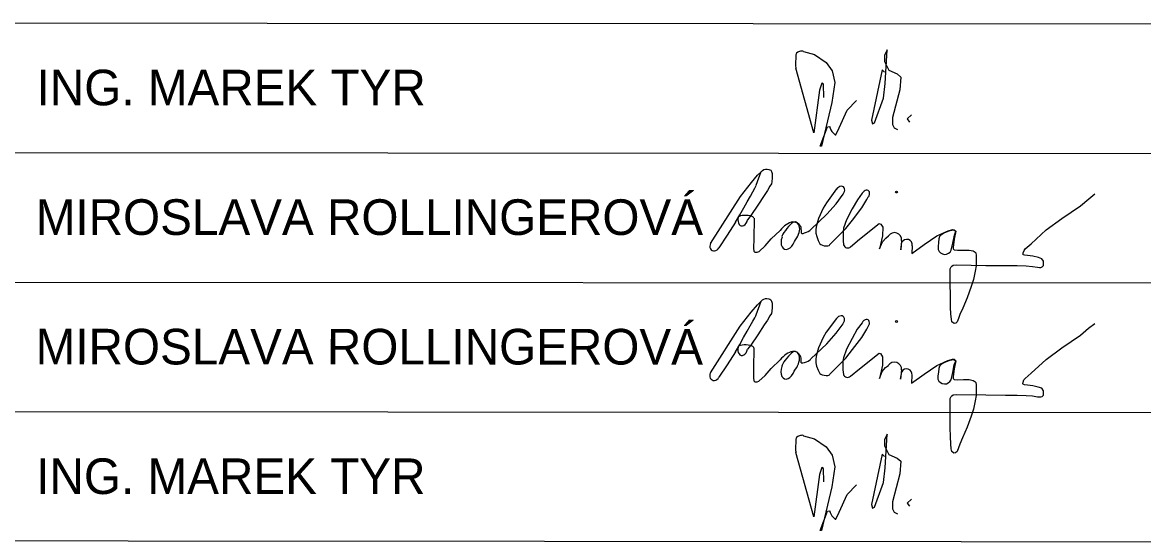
# Model space of a CAD drawing. Extents: x -467927 to -455912, y -1105662 to -1104439.
# Drawn here: x -458189.3 to -458127.1, y -1104681.1 to -1104652.6 of the extents above; entities that cross this region are included whole.
import ezdxf

# ---------------------------------------------------------------- set-up
doc = ezdxf.new("R2010")
doc.units = 0
doc.layers.add('Implicitní', color=7, linetype='Continuous')
doc.layers.add('Rozpiska TMS', color=7, linetype='Continuous')

msp = doc.modelspace()

# ---------------------------------------------------------------- linework, layer by layer
at = {"layer": 'Implicitní'}
for p, q in [((-458229.752, -1104659.823), (-458124.713, -1104659.9)), ((-458148.216, -1104660.849), (-458148.145, -1104660.795)), ((-458148.145, -1104660.795), (-458148.049, -1104660.77)), ((-458148.049, -1104660.77), (-458147.969, -1104660.77)), ((-458147.969, -1104660.77), (-458147.874, -1104660.788)), ((-458147.874, -1104660.788), (-458147.809, -1104660.811)), ((-458147.809, -1104660.811), (-458147.753, -1104660.835)), ((-458148.843, -1104661.525), (-458148.494, -1104661.115)), ((-458148.567, -1104661.672), (-458148.302, -1104660.914)), ((-458148.494, -1104661.115), (-458148.302, -1104660.921)), ((-458148.302, -1104660.921), (-458148.216, -1104660.849)), ((-458147.753, -1104660.835), (-458147.719, -1104660.909)), ((-458147.719, -1104660.909), (-458147.689, -1104661.02)), ((-458147.689, -1104661.258), (-458147.706, -1104661.473)), ((-458147.689, -1104661.02), (-458147.689, -1104661.258)), ((-458149.455, -1104662.298), (-458148.843, -1104661.525)), ((-458147.945, -1104661.963), (-458148.126, -1104662.238)), ((-458147.811, -1104661.728), (-458147.945, -1104661.963)), ((-458147.724, -1104661.597), (-458147.811, -1104661.728)), ((-458147.706, -1104661.473), (-458147.724, -1104661.597)), ((-458144.11, -1104661.879), (-458144.676, -1104662.641)), ((-458151.108, -1104664.902), (-458149.455, -1104662.298)), ((-458148.126, -1104662.238), (-458148.487, -1104662.779)), ((-458144.676, -1104662.641), (-458144.844, -1104662.938)), ((-458144.132, -1104662.701), (-458143.74, -1104662.168)), ((-458142.951, -1104662.475), (-458143.245, -1104662.987)), ((-458142.683, -1104662.116), (-458142.951, -1104662.475)), ((-458142.697, -1104662.932), (-458142.424, -1104662.472)), ((-458142.424, -1104662.472), (-458142.344, -1104662.32)), ((-458130.553, -1104662.809), (-458130.099, -1104662.423)), ((-458130.099, -1104662.423), (-458129.758, -1104662.151)), ((-458148.487, -1104662.779), (-458148.869, -1104663.355)), ((-458145.537, -1104664.123), (-458144.649, -1104663.277)), ((-458144.844, -1104662.938), (-458145.109, -1104663.516)), ((-458144.649, -1104663.277), (-458144.132, -1104662.701)), ((-458143.245, -1104662.987), (-458143.552, -1104663.586)), ((-458143.225, -1104663.606), (-458142.697, -1104662.932)), ((-458131.585, -1104663.513), (-458130.553, -1104662.809)), ((-458149.717, -1104663.723), (-458150.185, -1104664.448)), ((-458148.869, -1104663.355), (-458149.049, -1104663.589)), ((-458148.696, -1104663.5), (-458148.713, -1104664.65)), ((-458145.109, -1104663.516), (-458145.243, -1104663.979)), ((-458143.552, -1104663.586), (-458143.72, -1104664.054)), ((-458143.596, -1104664.084), (-458143.225, -1104663.606)), ((-458142.834, -1104664.672), (-458141.74, -1104663.805)), ((-458141.74, -1104663.805), (-458141.656, -1104663.829)), ((-458141.656, -1104663.829), (-458141.547, -1104663.999)), ((-458132.459, -1104664.149), (-458131.585, -1104663.513)), ((-458150.185, -1104664.448), (-458150.648, -1104665.145)), ((-458147.74, -1104664.65), (-458147.239, -1104664.179)), ((-458145.243, -1104663.979), (-458145.261, -1104664.152)), ((-458145.261, -1104664.152), (-458145.261, -1104664.337)), ((-458145.261, -1104664.337), (-458145.211, -1104664.529)), ((-458145.211, -1104664.529), (-458145.134, -1104664.742)), ((-458144.497, -1104664.992), (-458143.596, -1104664.084)), ((-458143.72, -1104664.054), (-458143.75, -1104664.241)), ((-458143.75, -1104664.241), (-458143.75, -1104664.725)), ((-458141.548, -1104664.475), (-458141.715, -1104665.207)), ((-458141.547, -1104663.999), (-458141.548, -1104664.475)), ((-458141.379, -1104664.608), (-458141.222, -1104664.492)), ((-458139.238, -1104664.967), (-458138.538, -1104664.484)), ((-458138.538, -1104664.484), (-458138.37, -1104664.413)), ((-458138.39, -1104664.521), (-458138.426, -1104664.648)), ((-458138.333, -1104664.457), (-458138.39, -1104664.521)), ((-458138.37, -1104664.413), (-458137.917, -1104664.203)), ((-458138.152, -1104664.342), (-458138.333, -1104664.457)), ((-458137.864, -1104664.224), (-458138.152, -1104664.342)), ((-458137.917, -1104664.203), (-458137.664, -1104664.14)), ((-458137.626, -1104664.175), (-458137.864, -1104664.224)), ((-458137.664, -1104664.14), (-458137.577, -1104664.145)), ((-458137.649, -1104664.886), (-458137.563, -1104664.448)), ((-458137.478, -1104664.225), (-458137.626, -1104664.175)), ((-458137.577, -1104664.145), (-458137.478, -1104664.225)), ((-458137.478, -1104664.225), (-458137.575, -1104664.675)), ((-458137.563, -1104664.448), (-458137.478, -1104664.225)), ((-458133.296, -1104664.924), (-458132.459, -1104664.149)), ((-458148.713, -1104664.65), (-458148.723, -1104665.176)), ((-458148.723, -1104665.176), (-458148.697, -1104665.338)), ((-458148.418, -1104665.352), (-458148.075, -1104665.037)), ((-458148.075, -1104665.037), (-458147.74, -1104664.65)), ((-458145.134, -1104664.742), (-458145.057, -1104664.889)), ((-458143.75, -1104664.725), (-458143.721, -1104664.993)), ((-458143.332, -1104665.091), (-458142.834, -1104664.672)), ((-458141.715, -1104665.207), (-458141.565, -1104664.824)), ((-458141.565, -1104664.824), (-458141.379, -1104664.608)), ((-458140.496, -1104664.737), (-458140.546, -1104665.257)), ((-458140.546, -1104665.257), (-458140.484, -1104664.835)), ((-458139.931, -1104665.472), (-458139.238, -1104664.967)), ((-458139.915, -1104665.03), (-458139.931, -1104665.472)), ((-458138.446, -1104664.86), (-458138.471, -1104665.072)), ((-458138.471, -1104665.072), (-458138.471, -1104665.247)), ((-458138.426, -1104664.648), (-458138.446, -1104664.86)), ((-458137.738, -1104665.286), (-458137.649, -1104664.886)), ((-458137.575, -1104664.675), (-458137.626, -1104665.127)), ((-458137.626, -1104665.127), (-458137.626, -1104665.21)), ((-458133.624, -1104665.213), (-458133.296, -1104664.924)), ((-458148.697, -1104665.338), (-458148.645, -1104665.394)), ((-458148.645, -1104665.394), (-458148.52, -1104665.394)), ((-458148.52, -1104665.394), (-458148.418, -1104665.352)), ((-458137.626, -1104665.21), (-458137.577, -1104665.267)), ((-458137.577, -1104665.267), (-458137.383, -1104665.287)), ((-458137.383, -1104665.287), (-458137.055, -1104665.271)), ((-458137.055, -1104665.271), (-458136.739, -1104665.271)), ((-458136.739, -1104665.271), (-458136.52, -1104665.314)), ((-458136.52, -1104665.314), (-458136.413, -1104665.384)), ((-458136.413, -1104665.384), (-458136.367, -1104665.435)), ((-458136.367, -1104665.435), (-458136.348, -1104665.568)), ((-458136.348, -1104665.568), (-458136.348, -1104665.849)), ((-458133.748, -1104665.501), (-458133.739, -1104665.421)), ((-458133.74, -1104665.535), (-458133.748, -1104665.501)), ((-458133.668, -1104665.561), (-458133.74, -1104665.535)), ((-458133.739, -1104665.421), (-458133.692, -1104665.289)), ((-458133.692, -1104665.289), (-458133.624, -1104665.213)), ((-458133.5, -1104665.579), (-458133.668, -1104665.561)), ((-458133.201, -1104665.614), (-458133.5, -1104665.579)), ((-458132.894, -1104665.686), (-458133.201, -1104665.614)), ((-458132.702, -1104665.756), (-458132.894, -1104665.686)), ((-458132.611, -1104665.894), (-458132.702, -1104665.756)), ((-458137.799, -1104666.319), (-458137.739, -1104666.205)), ((-458137.799, -1104666.5), (-458137.799, -1104666.319)), ((-458137.739, -1104666.205), (-458137.704, -1104666.17)), ((-458137.704, -1104666.17), (-458137.627, -1104666.118)), ((-458137.627, -1104666.118), (-458137.443, -1104666.093)), ((-458137.443, -1104666.093), (-458135.808, -1104666.128)), ((-458136.348, -1104666.158), (-458136.399, -1104666.445)), ((-458136.348, -1104665.849), (-458136.348, -1104666.158)), ((-458135.808, -1104666.128), (-458134.723, -1104666.135)), ((-458134.723, -1104666.135), (-458134.068, -1104666.135)), ((-458134.068, -1104666.135), (-458133.578, -1104666.156)), ((-458133.578, -1104666.156), (-458133.219, -1104666.183)), ((-458133.219, -1104666.183), (-458132.946, -1104666.229)), ((-458132.946, -1104666.229), (-458132.834, -1104666.234)), ((-458132.834, -1104666.234), (-458132.753, -1104666.234)), ((-458132.753, -1104666.234), (-458132.676, -1104666.203)), ((-458132.676, -1104666.203), (-458132.611, -1104666.136)), ((-458132.606, -1104666.039), (-458132.611, -1104665.894)), ((-458132.611, -1104666.136), (-458132.606, -1104666.039)), ((-458229.757, -1104667.023), (-458124.718, -1104667.1)), ((-458137.8, -1104666.996), (-458137.799, -1104666.5)), ((-458137.786, -1104667.938), (-458137.8, -1104666.996)), ((-458136.498, -1104666.908), (-458136.632, -1104667.304)), ((-458136.399, -1104666.445), (-458136.498, -1104666.908)), ((-458136.632, -1104667.304), (-458136.85, -1104667.923)), ((-458148.572, -1104668.872), (-458148.307, -1104668.114)), ((-458148.5, -1104668.315), (-458148.307, -1104668.121)), ((-458148.307, -1104668.121), (-458148.221, -1104668.049)), ((-458148.221, -1104668.049), (-458148.15, -1104667.995)), ((-458148.15, -1104667.995), (-458148.054, -1104667.97)), ((-458148.054, -1104667.97), (-458147.974, -1104667.97)), ((-458147.974, -1104667.97), (-458147.879, -1104667.988)), ((-458147.879, -1104667.988), (-458147.814, -1104668.011)), ((-458147.814, -1104668.011), (-458147.758, -1104668.035)), ((-458147.758, -1104668.035), (-458147.724, -1104668.109)), ((-458147.724, -1104668.109), (-458147.695, -1104668.22)), ((-458147.695, -1104668.22), (-458147.695, -1104668.458)), ((-458137.777, -1104668.445), (-458137.786, -1104667.938)), ((-458136.85, -1104667.923), (-458137.102, -1104668.503)), ((-458149.46, -1104669.498), (-458148.848, -1104668.725)), ((-458148.848, -1104668.725), (-458148.5, -1104668.315)), ((-458147.729, -1104668.797), (-458147.816, -1104668.928)), ((-458147.711, -1104668.673), (-458147.729, -1104668.797)), ((-458147.695, -1104668.458), (-458147.711, -1104668.673)), ((-458137.753, -1104668.844), (-458137.777, -1104668.445)), ((-458137.73, -1104669.116), (-458137.753, -1104668.844)), ((-458137.253, -1104668.855), (-458137.335, -1104669.068)), ((-458137.102, -1104668.503), (-458137.253, -1104668.855)), ((-458151.113, -1104672.102), (-458149.46, -1104669.498)), ((-458148.131, -1104669.438), (-458148.492, -1104669.979)), ((-458147.95, -1104669.163), (-458148.131, -1104669.438)), ((-458147.816, -1104668.928), (-458147.95, -1104669.163)), ((-458144.115, -1104669.079), (-458144.682, -1104669.841)), ((-458144.138, -1104669.901), (-458143.745, -1104669.368)), ((-458142.688, -1104669.316), (-458142.957, -1104669.675)), ((-458142.43, -1104669.672), (-458142.35, -1104669.52)), ((-458137.699, -1104669.27), (-458137.73, -1104669.116)), ((-458137.578, -1104669.359), (-458137.699, -1104669.27)), ((-458137.491, -1104669.34), (-458137.578, -1104669.359)), ((-458137.409, -1104669.271), (-458137.491, -1104669.34)), ((-458137.335, -1104669.068), (-458137.409, -1104669.271)), ((-458130.105, -1104669.623), (-458129.763, -1104669.351)), ((-458148.492, -1104669.979), (-458148.874, -1104670.555)), ((-458144.849, -1104670.138), (-458145.114, -1104670.716)), ((-458144.682, -1104669.841), (-458144.849, -1104670.138)), ((-458144.654, -1104670.477), (-458144.138, -1104669.901)), ((-458142.957, -1104669.675), (-458143.25, -1104670.187)), ((-458143.23, -1104670.806), (-458142.702, -1104670.132)), ((-458142.702, -1104670.132), (-458142.43, -1104669.672)), ((-458131.59, -1104670.713), (-458130.558, -1104670.009)), ((-458130.558, -1104670.009), (-458130.105, -1104669.623)), ((-458148.874, -1104670.555), (-458149.054, -1104670.789)), ((-458148.701, -1104670.7), (-458148.718, -1104671.85)), ((-458145.542, -1104671.323), (-458144.654, -1104670.477)), ((-458145.114, -1104670.716), (-458145.249, -1104671.179)), ((-458143.25, -1104670.187), (-458143.557, -1104670.786)), ((-458132.464, -1104671.349), (-458131.59, -1104670.713)), ((-458149.723, -1104670.923), (-458150.19, -1104671.648)), ((-458147.745, -1104671.85), (-458147.244, -1104671.379)), ((-458145.249, -1104671.179), (-458145.266, -1104671.352)), ((-458145.266, -1104671.352), (-458145.266, -1104671.537)), ((-458144.502, -1104672.192), (-458143.601, -1104671.284)), ((-458143.726, -1104671.254), (-458143.755, -1104671.441)), ((-458143.557, -1104670.786), (-458143.726, -1104671.254)), ((-458143.601, -1104671.284), (-458143.23, -1104670.806)), ((-458142.839, -1104671.872), (-458141.746, -1104671.005)), ((-458141.746, -1104671.005), (-458141.662, -1104671.029)), ((-458141.662, -1104671.029), (-458141.553, -1104671.199)), ((-458141.553, -1104671.199), (-458141.553, -1104671.675)), ((-458138.375, -1104671.613), (-458137.922, -1104671.403)), ((-458137.922, -1104671.403), (-458137.669, -1104671.34)), ((-458137.631, -1104671.375), (-458137.869, -1104671.424)), ((-458137.669, -1104671.34), (-458137.582, -1104671.345)), ((-458137.483, -1104671.424), (-458137.631, -1104671.375)), ((-458137.582, -1104671.345), (-458137.483, -1104671.424)), ((-458133.301, -1104672.124), (-458132.464, -1104671.349)), ((-458150.19, -1104671.648), (-458150.654, -1104672.345)), ((-458148.718, -1104671.85), (-458148.729, -1104672.376)), ((-458148.081, -1104672.237), (-458147.745, -1104671.85)), ((-458145.266, -1104671.537), (-458145.216, -1104671.729)), ((-458145.216, -1104671.729), (-458145.139, -1104671.942)), ((-458145.139, -1104671.942), (-458145.062, -1104672.089)), ((-458143.755, -1104671.441), (-458143.755, -1104671.925)), ((-458143.755, -1104671.925), (-458143.726, -1104672.193)), ((-458143.338, -1104672.291), (-458142.839, -1104671.872)), ((-458141.553, -1104671.675), (-458141.721, -1104672.407)), ((-458141.721, -1104672.407), (-458141.57, -1104672.024)), ((-458141.57, -1104672.024), (-458141.384, -1104671.808)), ((-458141.384, -1104671.808), (-458141.227, -1104671.692)), ((-458140.501, -1104671.937), (-458140.552, -1104672.457)), ((-458139.243, -1104672.167), (-458138.543, -1104671.684)), ((-458138.543, -1104671.684), (-458138.375, -1104671.613)), ((-458138.431, -1104671.848), (-458138.451, -1104672.06)), ((-458138.395, -1104671.721), (-458138.431, -1104671.848)), ((-458138.338, -1104671.657), (-458138.395, -1104671.721)), ((-458138.157, -1104671.542), (-458138.338, -1104671.657)), ((-458137.869, -1104671.424), (-458138.157, -1104671.542)), ((-458137.654, -1104672.086), (-458137.568, -1104671.648)), ((-458137.58, -1104671.875), (-458137.632, -1104672.327)), ((-458137.483, -1104671.424), (-458137.58, -1104671.875)), ((-458137.568, -1104671.648), (-458137.483, -1104671.424)), ((-458148.729, -1104672.376), (-458148.703, -1104672.538)), ((-458148.703, -1104672.538), (-458148.651, -1104672.594)), ((-458148.651, -1104672.594), (-458148.526, -1104672.594)), ((-458148.526, -1104672.594), (-458148.424, -1104672.552)), ((-458148.424, -1104672.552), (-458148.081, -1104672.237)), ((-458140.552, -1104672.457), (-458140.489, -1104672.035)), ((-458139.936, -1104672.672), (-458139.243, -1104672.167)), ((-458139.92, -1104672.23), (-458139.936, -1104672.672)), ((-458138.451, -1104672.06), (-458138.477, -1104672.272)), ((-458138.477, -1104672.272), (-458138.477, -1104672.447)), ((-458137.744, -1104672.486), (-458137.654, -1104672.086)), ((-458137.632, -1104672.327), (-458137.632, -1104672.41)), ((-458137.632, -1104672.41), (-458137.583, -1104672.467)), ((-458137.583, -1104672.467), (-458137.389, -1104672.487)), ((-458137.389, -1104672.487), (-458137.061, -1104672.471)), ((-458137.061, -1104672.471), (-458136.745, -1104672.471)), ((-458136.745, -1104672.471), (-458136.526, -1104672.514)), ((-458136.526, -1104672.514), (-458136.419, -1104672.584)), ((-458136.419, -1104672.584), (-458136.373, -1104672.635)), ((-458136.373, -1104672.635), (-458136.353, -1104672.768)), ((-458133.753, -1104672.701), (-458133.745, -1104672.621)), ((-458133.745, -1104672.621), (-458133.698, -1104672.489)), ((-458133.698, -1104672.489), (-458133.63, -1104672.413)), ((-458133.63, -1104672.413), (-458133.301, -1104672.124)), ((-458136.353, -1104672.768), (-458136.353, -1104673.049)), ((-458136.353, -1104673.049), (-458136.353, -1104673.358)), ((-458133.745, -1104672.735), (-458133.753, -1104672.701)), ((-458133.673, -1104672.761), (-458133.745, -1104672.735)), ((-458133.505, -1104672.779), (-458133.673, -1104672.761)), ((-458133.206, -1104672.814), (-458133.505, -1104672.779)), ((-458132.899, -1104672.886), (-458133.206, -1104672.814)), ((-458132.707, -1104672.956), (-458132.899, -1104672.886)), ((-458132.616, -1104673.094), (-458132.707, -1104672.956)), ((-458132.611, -1104673.239), (-458132.616, -1104673.094)), ((-458132.616, -1104673.336), (-458132.611, -1104673.239)), ((-458137.805, -1104673.7), (-458137.804, -1104673.519)), ((-458137.805, -1104674.196), (-458137.805, -1104673.7)), ((-458137.804, -1104673.519), (-458137.744, -1104673.405)), ((-458137.744, -1104673.405), (-458137.709, -1104673.37)), ((-458137.709, -1104673.37), (-458137.632, -1104673.318)), ((-458137.632, -1104673.318), (-458137.448, -1104673.293)), ((-458137.448, -1104673.293), (-458135.813, -1104673.328)), ((-458136.405, -1104673.645), (-458136.503, -1104674.108)), ((-458136.353, -1104673.358), (-458136.405, -1104673.645)), ((-458135.813, -1104673.328), (-458134.728, -1104673.335)), ((-458134.728, -1104673.335), (-458134.073, -1104673.335)), ((-458134.073, -1104673.335), (-458133.583, -1104673.356)), ((-458133.583, -1104673.356), (-458133.224, -1104673.383)), ((-458133.224, -1104673.383), (-458132.951, -1104673.429)), ((-458132.951, -1104673.429), (-458132.839, -1104673.434)), ((-458132.839, -1104673.434), (-458132.758, -1104673.434)), ((-458132.758, -1104673.434), (-458132.681, -1104673.403)), ((-458132.681, -1104673.403), (-458132.616, -1104673.336)), ((-458229.763, -1104674.223), (-458124.724, -1104674.3)), ((-458137.792, -1104675.138), (-458137.805, -1104674.196)), ((-458136.637, -1104674.504), (-458136.856, -1104675.123)), ((-458136.503, -1104674.108), (-458136.637, -1104674.504)), ((-458137.782, -1104675.645), (-458137.792, -1104675.138)), ((-458136.856, -1104675.123), (-458137.107, -1104675.703)), ((-458137.758, -1104676.044), (-458137.782, -1104675.645)), ((-458137.107, -1104675.703), (-458137.258, -1104676.055)), ((-458137.736, -1104676.316), (-458137.758, -1104676.044)), ((-458137.705, -1104676.47), (-458137.736, -1104676.316)), ((-458137.34, -1104676.268), (-458137.415, -1104676.471)), ((-458137.258, -1104676.055), (-458137.34, -1104676.268)), ((-458137.584, -1104676.559), (-458137.705, -1104676.47)), ((-458137.497, -1104676.54), (-458137.584, -1104676.559)), ((-458137.415, -1104676.471), (-458137.497, -1104676.54))]:
    msp.add_line(p, q, dxfattribs=at)
msp.add_lwpolyline([(-458229.747, -1104652.623), (-458067.742, -1104652.742), (-458067.763, -1104681.543), (-458229.768, -1104681.424)], close=True, dxfattribs=at)
for centre in [(-458140.774, -1104662.048), (-458140.78, -1104669.248)]:
    msp.add_circle(centre, 0.0535, dxfattribs=at)
for centre, radius, start, end in [((-458140.891, -1104664.707), 0.4, 355.78467, 147.22874), ((-458143.492, -1104664.915), 0.238, 197.54011, 313.10888), ((-458140.216, -1104664.988), 0.309, 352.16792, 150.33963), ((-458138.096, -1104665.118), 0.394, 199.70252, 334.88277), ((-458140.896, -1104671.907), 0.4, 355.78467, 147.22874), ((-458140.222, -1104672.188), 0.309, 352.16792, 150.33963), ((-458143.497, -1104672.115), 0.238, 197.54011, 313.10888), ((-458138.102, -1104672.318), 0.394, 199.70252, 334.88277)]:
    msp.add_arc(centre, radius, start, end, dxfattribs=at)
for centre, major_axis, ratio, start_param, end_param in [((-458149.74, -1104663.714), (1.171, 2.036), 0.009505, 4.712389, 6.283185), ((-458143.926, -1104662.022), (-0.194, -0.258), 0.719657, 1.570796, 4.712389), ((-458142.512, -1104662.218), (-0.159, -0.26), 0.66672, 1.570796, 4.712389), ((-458149.313, -1104663.529), (-0.091, -0.4), 0.65459, 4.712389, 7.853982), ((-458149.14, -1104663.487), (0.435, -0.017), 0.329233, 6.283185, 9.424778), ((-458146.847, -1104664.49), (0.566, 0.719), 0.546541, 4.712389, 7.853982), ((-458146.796, -1104664.135), (0.343, 0.419), 0.173859, 0, 3.141593), ((-458146.232, -1104664.057), (-0.221, 0.341), 0.392654, 4.712389, 6.283185), ((-458146.796, -1104664.676), (-0.198, -0.551), 0.62126, 4.712389, 7.853982), ((-458146.105, -1104664.333), (0.006, 0.363), 0.109468, 4.712389, 6.283185), ((-458145.803, -1104664.228), (0.262, 0.106), 0.227956, 3.141593, 6.283185), ((-458150.877, -1104665.023), (-0.143, -0.271), 0.856584, 4.712389, 7.853982), ((-458144.774, -1104664.944), (0.279, -0.051), 0.318058, 3.141593, 6.283185), ((-458149.745, -1104670.914), (1.171, 2.036), 0.009505, 4.712389, 6.283185), ((-458143.931, -1104669.222), (-0.194, -0.258), 0.719657, 1.570796, 4.712389), ((-458142.517, -1104669.418), (-0.159, -0.26), 0.66672, 1.570796, 4.712389), ((-458149.319, -1104670.729), (-0.091, -0.4), 0.65459, 4.712389, 7.853982), ((-458149.145, -1104670.687), (0.435, -0.017), 0.329233, 6.283185, 9.424778), ((-458146.852, -1104671.69), (0.566, 0.719), 0.546541, 4.712389, 7.853982), ((-458146.801, -1104671.335), (0.343, 0.419), 0.173859, 0, 3.141593), ((-458146.238, -1104671.257), (-0.221, 0.341), 0.392654, 4.712389, 6.283185), ((-458146.11, -1104671.533), (0.006, 0.363), 0.109468, 4.712389, 6.283185), ((-458145.808, -1104671.428), (0.262, 0.106), 0.227956, 3.141593, 6.283185), ((-458146.802, -1104671.876), (-0.198, -0.551), 0.62126, 4.712389, 7.853982), ((-458150.883, -1104672.223), (-0.143, -0.271), 0.856584, 4.712389, 7.853982), ((-458144.779, -1104672.144), (0.279, -0.051), 0.318058, 3.141593, 6.283185)]:
    msp.add_ellipse(centre, major_axis=major_axis, ratio=ratio, start_param=start_param, end_param=end_param, dxfattribs=at)
at = {"layer": 'Rozpiska TMS'}
for p, q in [((-458145.944, -1104654.234), (-458145.335, -1104654.407)), ((-458145.335, -1104654.407), (-458144.679, -1104654.845)), ((-458141.29, -1104654.141), (-458141.447, -1104654.453)), ((-458141.447, -1104654.453), (-458141.447, -1104654.797)), ((-458141.4, -1104656.016), (-458141.29, -1104654.141)), ((-458145.381, -1104658.751), (-458146.366, -1104655.172)), ((-458144.679, -1104654.845), (-458144.351, -1104655.313)), ((-458141.447, -1104654.797), (-458141.212, -1104655.281)), ((-458144.351, -1104655.313), (-458144.21, -1104655.954)), ((-458141.571, -1104655.266), (-458142.164, -1104658.064)), ((-458141.447, -1104655.391), (-458141.571, -1104655.266)), ((-458141.212, -1104655.281), (-458140.743, -1104655.485)), ((-458140.743, -1104655.485), (-458140.54, -1104655.657)), ((-458140.54, -1104655.657), (-458140.602, -1104656.36)), ((-458145.054, -1104656.391), (-458145.381, -1104658.751)), ((-458144.929, -1104656.001), (-458145.054, -1104656.391)), ((-458144.835, -1104656.048), (-458144.929, -1104656.001)), ((-458144.819, -1104656.798), (-458144.835, -1104656.048)), ((-458144.21, -1104655.954), (-458144.367, -1104657.08)), ((-458141.509, -1104656.828), (-458141.4, -1104656.016)), ((-458140.602, -1104656.36), (-458141.008, -1104657.908)), ((-458144.367, -1104657.08), (-458144.944, -1104659.502)), ((-458143.523, -1104657.502), (-458143.008, -1104656.97)), ((-458141.993, -1104658.205), (-458141.509, -1104656.828)), ((-458143.96, -1104658.486), (-458143.523, -1104657.502)), ((-458142.164, -1104658.064), (-458142.103, -1104658.267)), ((-458142.103, -1104658.267), (-458141.993, -1104658.205)), ((-458141.008, -1104657.908), (-458141.008, -1104658.299)), ((-458141.008, -1104658.299), (-458140.9, -1104658.486)), ((-458139.946, -1104657.767), (-458140.18, -1104657.986)), ((-458140.18, -1104657.986), (-458140.057, -1104658.158)), ((-458145.023, -1104659.502), (-458144.616, -1104658.423)), ((-458144.616, -1104658.423), (-458144.476, -1104658.409)), ((-458144.148, -1104658.877), (-458143.96, -1104658.486)), ((-458140.9, -1104658.486), (-458140.729, -1104658.58)), ((-458144.944, -1104659.502), (-458145.023, -1104659.502)), ((-458145.944, -1104675.591), (-458145.335, -1104675.764)), ((-458145.335, -1104675.764), (-458144.679, -1104676.202)), ((-458141.29, -1104675.498), (-458141.447, -1104675.811)), ((-458141.4, -1104677.373), (-458141.29, -1104675.498)), ((-458144.679, -1104676.202), (-458144.351, -1104676.67)), ((-458141.447, -1104675.811), (-458141.447, -1104676.154)), ((-458141.447, -1104676.154), (-458141.212, -1104676.638)), ((-458145.381, -1104680.108), (-458146.366, -1104676.529)), ((-458144.351, -1104676.67), (-458144.21, -1104677.312)), ((-458141.571, -1104676.623), (-458142.164, -1104679.421)), ((-458141.447, -1104676.749), (-458141.571, -1104676.623)), ((-458141.212, -1104676.638), (-458140.743, -1104676.843)), ((-458140.743, -1104676.843), (-458140.54, -1104677.014)), ((-458140.54, -1104677.014), (-458140.602, -1104677.717)), ((-458144.929, -1104677.358), (-458145.054, -1104677.748)), ((-458144.835, -1104677.405), (-458144.929, -1104677.358)), ((-458144.819, -1104678.155), (-458144.835, -1104677.405)), ((-458144.21, -1104677.312), (-458144.367, -1104678.437)), ((-458141.509, -1104678.186), (-458141.4, -1104677.373)), ((-458145.054, -1104677.748), (-458145.381, -1104680.108)), ((-458141.993, -1104679.562), (-458141.509, -1104678.186)), ((-458140.602, -1104677.717), (-458141.008, -1104679.265)), ((-458144.367, -1104678.437), (-458144.944, -1104680.859)), ((-458143.96, -1104679.844), (-458143.523, -1104678.859)), ((-458143.523, -1104678.859), (-458143.008, -1104678.327)), ((-458142.164, -1104679.421), (-458142.103, -1104679.624)), ((-458141.008, -1104679.265), (-458141.008, -1104679.656)), ((-458139.946, -1104679.124), (-458140.18, -1104679.343)), ((-458140.18, -1104679.343), (-458140.057, -1104679.515)), ((-458145.023, -1104680.859), (-458144.616, -1104679.78)), ((-458144.616, -1104679.78), (-458144.476, -1104679.766)), ((-458144.148, -1104680.234), (-458143.96, -1104679.844)), ((-458142.103, -1104679.624), (-458141.993, -1104679.562)), ((-458141.008, -1104679.656), (-458140.9, -1104679.844)), ((-458140.9, -1104679.844), (-458140.729, -1104679.938)), ((-458144.944, -1104680.859), (-458145.023, -1104680.859))]:
    msp.add_line(p, q, dxfattribs=at)
for centre, major_axis, ratio, start_param, end_param in [((-458146.358, -1104654.774), (0.008, 0.399), 0.064441, 0, 3.141593), ((-458146.147, -1104654.305), (0.203, 0.07), 0.314219, 0, 3.141593), ((-458144.312, -1104658.642), (0.164, -0.234), 0.219584, 3.141593, 6.283185), ((-458146.358, -1104676.131), (0.008, 0.399), 0.064441, 0, 3.141593), ((-458146.147, -1104675.662), (0.203, 0.07), 0.314219, 0, 3.141593), ((-458144.312, -1104679.999), (0.164, -0.234), 0.219584, 3.141593, 6.283185)]:
    msp.add_ellipse(centre, major_axis=major_axis, ratio=ratio, start_param=start_param, end_param=end_param, dxfattribs=at)

# ---------------------------------------------------------------- texts
at = {"layer": 'Implicitní'}
for s, p in [('ING. MAREK TYR', (-458188.558, -1104657.23)), ('MIROSLAVA ROLLINGEROVÁ', (-458188.606, -1104664.43)), ('MIROSLAVA ROLLINGEROVÁ', (-458188.611, -1104671.63)), ('ING. MAREK TYR', (-458188.574, -1104678.831))]:
    msp.add_text(s, height=1.98, rotation=359.9912, dxfattribs=at).set_placement(p)

doc.saveas('drawing.dxf')
